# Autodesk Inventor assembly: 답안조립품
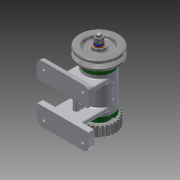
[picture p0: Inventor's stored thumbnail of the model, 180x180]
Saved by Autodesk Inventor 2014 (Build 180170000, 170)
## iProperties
Created: 2016-07
Part Number: 답안조립품
Document SubType Name: Assembly
Designer: user
Author: user
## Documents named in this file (14)
- C:\Users\user\Desktop\460708V1029\답안조립품.iam
- C:\Users\user\Desktop\460708V1029\본체.ipt
- C:\Users\user\Desktop\460708V1029\커버.ipt
- C:\Users\user\Desktop\460708V1029\축.ipt
- C:\Users\user\Desktop\460708V1029\키 3 x 3 x 12.ipt
- C:\Users\user\Desktop\460708V1029\V벨트풀리.ipt
- C:\Users\user\Desktop\460708V1029\스퍼기어.ipt
- C:\Users\user\Desktop\460708V1029\와셔 8x17.ipt
- C:\Users\user\Desktop\460708V1029\스프링와셔 8.ipt
- C:\Users\user\Desktop\460708V1029\너트 M 8.ipt
- C:\Users\user\Desktop\460708V1029\볼트 M4 x 12.ipt
- C:\Users\user\Desktop\460708V1029\오일 실 15 25 7.ipt
- C:\Users\user\Desktop\460708V1029\베어링 15 x 32 x 9.ipt
- C:\Users\user\Desktop\460708V1029\니플 M 6 x 0.75.ipt
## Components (11 placed, 3 different names)
1. V벨트풀리:1 — Mate:5, Mate:6, Insert:5, Insert:11
2. KS B 2023 6002 - 15 x 32 x 9:1 — Insert:17
3. KS B 2023 6002 - 15 x 32 x 9:2 — Insert:18, Insert:21
4. ISO 4762 M4 x 12:1 — Insert:15
5. ISO 4762 M4 x 12:3
6. ISO 4762 M4 x 12:4
7. ISO 4762 M4 x 12:5
8. ISO 4762 M4 x 12:2 — Insert:16
9. ISO 4762 M4 x 12:6
10. ISO 4762 M4 x 12:7
11. ISO 4762 M4 x 12:8
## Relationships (9: Insert 7, Mate 2)
- Mate:5: V벨트풀리:1
- Mate:6: V벨트풀리:1
- Insert:5: V벨트풀리:1
- Insert:11: V벨트풀리:1
- Insert:15: ISO 4762 M4 x 12:1
- Insert:16: ISO 4762 M4 x 12:2
- Insert:17: KS B 2023 6002 - 15 x 32 x 9:1
- Insert:18: KS B 2023 6002 - 15 x 32 x 9:2
- Insert:21: KS B 2023 6002 - 15 x 32 x 9:2
